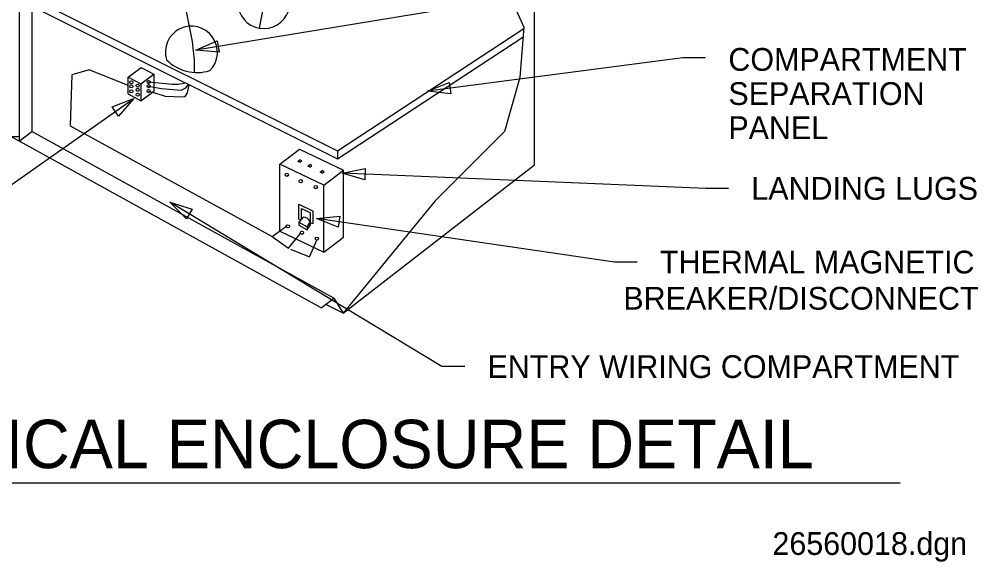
# Model space of a CAD drawing. Extents: x 10314 to 10360.8, y 10093.4 to 10137.8.
# Drawn here: x 10332.56 to 10360.64, y 10093.42 to 10109.31 of the extents above; entities that cross this region are included whole.
import ezdxf

# ---------------------------------------------------------------- set-up
doc = ezdxf.new("R2010")
doc.units = 0
for name, color, linetype in [('G-ANNO-TEXT', 7, 'Continuous'), ('G-DETL-LINE', 7, 'Continuous'), ('G-DETL-OTLN', 7, 'Continuous')]:
    doc.layers.add(name, color=color, linetype=linetype)

msp = doc.modelspace()

# ---------------------------------------------------------------- linework, layer by layer
at = {"layer": 'G-ANNO-TEXT'}
for p, q in [((10348.129, 10110.106), (10337.729, 10108.395)), ((10351.997, 10108.17), (10344.516, 10107.202)), ((10352.664, 10108.17), (10351.997, 10108.17)), ((10323.781, 10098.443), (10335.921, 10106.987)), ((10352.669, 10104.354), (10342.022, 10104.802)), ((10353.336, 10104.354), (10352.669, 10104.354)), ((10344.942, 10099.137), (10336.972, 10103.949)), ((10349.992, 10102.197), (10341.265, 10103.475)), ((10350.659, 10102.197), (10349.992, 10102.197)), ((10345.609, 10099.137), (10344.942, 10099.137)), ((10316.777, 10095.732), (10358.361, 10095.732))]:
    msp.add_line(p, q, dxfattribs=at)
for points in [[(10338.414, 10108.338), (10337.729, 10108.395), (10338.36, 10108.667)], [(10345.198, 10107.122), (10344.516, 10107.202), (10345.155, 10107.453)], [(10335.28, 10106.74), (10335.921, 10106.987), (10335.472, 10106.467)], [(10342.681, 10104.607), (10342.022, 10104.802), (10342.695, 10104.94)], [(10337.456, 10103.462), (10336.972, 10103.949), (10337.629, 10103.747)], [(10341.9, 10103.214), (10341.265, 10103.475), (10341.948, 10103.544)]]:
    msp.add_lwpolyline(points, close=True, dxfattribs=at)
at = {"layer": 'G-DETL-LINE'}
for p, q in [((10346.888, 10110.091), (10347.34, 10109.073)), ((10347.34, 10109.073), (10347.227, 10107.603)), ((10335.751, 10107.612), (10336.131, 10107.894)), ((10336.131, 10107.894), (10336.504, 10107.692)), ((10335.751, 10107.612), (10336.124, 10107.41)), ((10335.751, 10107.117), (10335.751, 10107.612)), ((10336.124, 10107.41), (10336.504, 10107.692)), ((10336.504, 10107.692), (10336.504, 10107.197)), ((10347.227, 10107.603), (10346.775, 10106.02)), ((10336.124, 10107.41), (10336.124, 10106.915)), ((10336.124, 10106.915), (10336.504, 10107.197)), ((10335.751, 10107.117), (10336.124, 10106.915)), ((10346.775, 10106.02), (10344.742, 10103.985)), ((10340.722, 10105.144), (10340.78, 10105.188)), ((10340.839, 10105.16), (10340.78, 10105.188)), ((10340.781, 10105.116), (10340.722, 10105.144)), ((10340.781, 10105.116), (10340.839, 10105.16)), ((10341.015, 10105.007), (10341.073, 10105.051)), ((10341.074, 10104.979), (10341.015, 10105.007)), ((10341.132, 10105.023), (10341.073, 10105.051)), ((10341.074, 10104.979), (10341.132, 10105.023)), ((10341.378, 10104.829), (10341.436, 10104.873)), ((10341.437, 10104.801), (10341.378, 10104.829)), ((10341.495, 10104.845), (10341.436, 10104.873)), ((10341.437, 10104.801), (10341.495, 10104.845)), ((10340.75, 10103.45), (10340.75, 10103.889)), ((10340.75, 10103.889), (10341.174, 10103.687)), ((10344.742, 10103.985), (10342.047, 10100.701)), ((10340.881, 10103.515), (10340.75, 10103.366)), ((10340.828, 10103.45), (10340.828, 10103.765)), ((10340.828, 10103.765), (10341.095, 10103.638)), ((10341.095, 10103.284), (10341.095, 10103.638)), ((10341.174, 10103.323), (10341.174, 10103.687)), ((10340.75, 10103.45), (10340.808, 10103.433)), ((10340.75, 10103.366), (10340.75, 10103.276)), ((10340.75, 10103.366), (10340.991, 10103.228)), ((10340.75, 10103.276), (10340.991, 10103.138)), ((10340.991, 10103.228), (10341.091, 10103.37)), ((10340.991, 10103.138), (10341.095, 10103.284)), ((10340.991, 10103.228), (10340.991, 10103.138)), ((10341.095, 10103.347), (10341.174, 10103.323))]:
    msp.add_line(p, q, dxfattribs=at)
for centre, radius in [((10335.842, 10107.46), 0.0457), ((10336.352, 10107.467), 0.0457), ((10335.842, 10107.338), 0.0457), ((10335.842, 10107.193), 0.0457), ((10336.032, 10107.361), 0.0457), ((10336.032, 10107.239), 0.0457), ((10336.352, 10107.345), 0.0457), ((10336.352, 10107.201), 0.0457), ((10336.032, 10107.094), 0.0457), ((10340.399, 10104.752), 0.0471), ((10340.807, 10104.563), 0.0471), ((10341.247, 10104.391), 0.0471), ((10340.431, 10103.244), 0.0471), ((10340.839, 10103.055), 0.0471), ((10341.278, 10102.883), 0.0471)]:
    msp.add_circle(centre, radius, dxfattribs=at)
for centre, radius, start, end in [((10339.724, 10109.791), 0.762, 109.4878, 351.4682), ((10337.604, 10108.339), 0.762, 314.9651, 196.9455), ((10337.768, 10108.996), 1.253, 224.5496, 287.361), ((10340.864, 10103.265), 0.25, 24.7333, 86.1326)]:
    msp.add_arc(centre, radius, start, end, dxfattribs=at)
at = {"layer": 'G-DETL-OTLN'}
for p, q in [((10347.649, 10105.044), (10347.649, 10133.422)), ((10332.562, 10132.634), (10332.562, 10105.735)), ((10332.933, 10132.418), (10332.933, 10106.019)), ((10333.012, 10109.891), (10341.879, 10105.455)), ((10333.012, 10109.651), (10341.879, 10105.215)), ((10341.879, 10105.455), (10347.337, 10109.034)), ((10341.879, 10105.215), (10347.337, 10108.794)), ((10341.402, 10100.853), (10332.318, 10105.87)), ((10332.562, 10105.735), (10332.933, 10106.019)), ((10341.773, 10101.137), (10332.933, 10106.019)), ((10340.193, 10105.064), (10340.774, 10105.504)), ((10340.774, 10105.504), (10342.062, 10104.891)), ((10341.879, 10105.455), (10341.879, 10105.215)), ((10340.193, 10103.1), (10340.193, 10105.064)), ((10341.481, 10104.451), (10340.193, 10105.064)), ((10342.047, 10100.701), (10347.649, 10105.044)), ((10341.481, 10104.451), (10342.062, 10104.891)), ((10342.062, 10102.927), (10342.062, 10104.891)), ((10341.481, 10102.487), (10341.481, 10104.451)), ((10340.193, 10103.1), (10341.481, 10102.487)), ((10341.481, 10102.487), (10342.062, 10102.927)), ((10341.402, 10100.853), (10341.773, 10101.137)), ((10341.773, 10101.137), (10342.047, 10100.701)), ((10342.047, 10100.701), (10341.537, 10100.956))]:
    msp.add_line(p, q, dxfattribs=at)
for points in [[(10332.562, 10132.634), (10332.562, 10105.735), (10332.318, 10105.87), (10332.324, 10132.724)], [(10332.318, 10105.87), (10332.562, 10105.87), (10332.562, 10105.735)]]:
    msp.add_lwpolyline(points, close=True, dxfattribs=at)
for points in [[(10337.106, 10111.771), (10337.534, 10111.557), (10337.804, 10111.437), (10338.164, 10111.317), (10338.553, 10111.167), (10339.033, 10111.107), (10339.183, 10111.077), (10339.483, 10110.927), (10339.633, 10111.047), (10339.843, 10110.657), (10339.813, 10110.298), (10339.813, 10110.178), (10339.603, 10109.098), (10339.603, 10109.039)], [(10337.21, 10111.719), (10337.444, 10109.578), (10337.624, 10108.648), (10337.684, 10108.108), (10337.684, 10107.748), (10337.683, 10107.746)], [(10335.751, 10107.364), (10334.612, 10107.822), (10334.105, 10107.681), (10334.049, 10106.186), (10339.968, 10102.943), (10340.362, 10103.225)], [(10336.352, 10107.467), (10337.045, 10107.406), (10337.22, 10107.406), (10337.395, 10107.429), (10337.426, 10107.443)], [(10336.352, 10107.345), (10336.725, 10107.277), (10336.953, 10107.254), (10337.303, 10107.223), (10337.44, 10107.292), (10337.509, 10107.383), (10337.518, 10107.397)], [(10336.352, 10107.201), (10336.588, 10107.132), (10336.839, 10107.056), (10337.083, 10107.041), (10337.243, 10107.033), (10337.418, 10107.041), (10337.486, 10107.147), (10337.517, 10107.3), (10337.54, 10107.386)], [(10339.968, 10102.943), (10340.447, 10102.605), (10340.785, 10103.028)], [(10340.503, 10102.577), (10341.067, 10102.351), (10341.292, 10102.859)]]:
    msp.add_lwpolyline(points, dxfattribs=at)

# ---------------------------------------------------------------- texts
at = {"layer": 'G-ANNO-TEXT'}
for s, height, p in [('COMPARTMENT ', 0.66667, (10353.331, 10107.795)), ('SEPARATION', 0.6667, (10353.331, 10106.795)), ('PANEL', 0.6667, (10353.331, 10105.795)), ('LANDING LUGS', 0.66667, (10354.003, 10104.02)), ('THERMAL MAGNETIC', 0.66667, (10351.326, 10101.864)), ('BREAKER/DISCONNECT', 0.66667, (10350.255, 10100.804)), ('ENTRY WIRING COMPARTMENT', 0.66667, (10346.276, 10098.804)), ('MUSCO ELECTRICAL ENCLOSURE DETAIL', 1.41667, (10317.094, 10096.165)), ('26560018.dgn', 0.66667, (10354.621, 10093.626))]:
    msp.add_text(s, height=height, dxfattribs=at).set_placement(p)

doc.saveas('drawing.dxf')
